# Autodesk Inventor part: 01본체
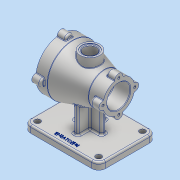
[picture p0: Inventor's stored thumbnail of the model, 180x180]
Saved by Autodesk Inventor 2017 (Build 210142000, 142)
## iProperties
Part Number: 01본체
Material: 알루미늄 6061
Document SubType Name: Modeling
Designer: 222
Density: 2.7 g/cm^3
Appearance: 알루미늄 - 평지
Mass: 1030.13 g
Surface Area: 850.653 cm^2
Volume: 381.528 cm^3
Author: 222
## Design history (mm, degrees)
sketch "스케치1"
  geometry: L1 (0, 0)-(0, 27.5); L2 (0, 27.5)-(-25, 27.5); L3 (-25, 27.5)-(-80, 44); L4 (-80, 44)-(-100, 44); L5 (-100, 44)-(-100, 0); L6 (-100, 0)-(0, 0)
  constraints: 12 end point, 3 perpendicular, 1 parallel, 1 vertical
  dimensions: "d0" = 100 distance of L5.end L1.start; "d1" = 55 diameter of L2 L6; "d2" = 88 diameter of L4 L6; "d3" = 20 distance of L3.end L4.end; "d4" = 25 distance of L1.end L2.end
revolve "회전1" sketch "스케치1" stored, may be unused: angle "d5" = 90 deg
node "작업 평면1"
node "작업 평면2"
sketch "스케치2"
  geometry: L1 (-115, 50)-(15, 50); L2 (15, 50)-(15, -50); L3 (15, -50)-(-115, -50); L4 (-115, -50)-(-115, 50); L5 (-50, 70)-(-50, -70) reference; 3 further points
  constraints: 8 end point, 2 midpoint, 2 parallel, 1 horizontal, 1 horizontal alignment, 1 perpendicular, 1 point on line
  dimensions: "d7" = 130 distance of L1.start L1.end; "d8" = 100 distance of L1.end L2.end
extrude "돌출1" join sketch "스케치2" distance "d9" = 12; taper "d10" = 0 deg
fillet "모깎기1" dims "d11" = 12
sketch "스케치3"
  geometry: L1 (-74, 4)-(-26, 4); L2 (-26, 4)-(-26, -4); L3 (-26, -4)-(-74, -4); L4 (-74, -4)-(-74, 4); L5 (-46, -25)-(-54, -25); L6 (-54, -25)-(-54, 25); L7 (-54, 25)-(-46, 25); L8 (-46, 25)-(-46, -25); L9 (-103, 50)-(3, 50) reference; 6 further points
  constraints: 16 end point, 5 midpoint, 4 parallel, 2 horizontal, 2 horizontal alignment, 2 perpendicular, 2 vertical alignment
  dimensions: "d12" = 8 distance of L6.end L7.end; "d13" = 8 distance of L3.end L1.start; "d14" = 48 distance of L2.end L3.end; "d15" = 50 distance of L7.end L5.start
extrude "돌출2" join sketch "스케치3" stored distance "d16" = 12; taper "d17" = 0 deg
sketch "스케치4"
  geometry: C1 r 7 at (44, 0); 2 further points
  constraints: 1 centre point, 1 horizontal alignment, 1 other
  dimensions: "d18" = 14 diameter of C1
extrude "돌출3" join sketch "스케치4" distance "d19" = 15; taper "d20" = 0 deg
sketch "스케치5"
  geometry: 3 further points
  constraints: 2 horizontal alignment, 1 other
hole "구멍1" sketch "스케치5" at (0, 0) diameter "d21" = 4.134; stored, may be unused: countersink angle "d25" = 90 deg, drill point angle "d27" = 118 deg; dims "d22" = 9, "d23" = 4, "d24" = 2, "d26" = 11
sketch "스케치6"
  geometry: C1 r 7 at (-27.5, 0); A1 r 27.5 centre (0, 0) between (-27.5, 0) and (27.208, 4) reference; 2 further points
  constraints: 1 centre point, 1 point on circle
  dimensions: "d31" = 14 diameter of C1
extrude "돌출4" join sketch "스케치6" distance "d32" = 15; taper "d33" = 0 deg
sketch "스케치7"
  geometry: A1 r 27.5 centre (27.5, 0) between (0, 0) and (0, 0) reference; 3 further points
  constraints: 2 horizontal alignment, 2 point on circle
hole "구멍2" sketch "스케치7" at (0, 0) diameter "d34" = 4.134; stored, may be unused: countersink angle "d38" = 90 deg, drill point angle "d40" = 118 deg; dims "d35" = 9, "d36" = 4, "d37" = 2, "d39" = 11
sketch "스케치8"
  geometry: C1 r 32 at (-44, 0); 1 further point
  constraints: 1 centre point, 1 coincident
  dimensions: "d44" = 64 diameter of C1
extrude "돌출5" cut sketch "스케치8" distance "d45" = 23; taper "d46" = 0 deg
sketch "스케치9"
  geometry: C1 r 26 at (0, 0); 1 further point
  constraints: 1 centre point, 1 coincident
  dimensions: "d47" = 52 diameter of C1
extrude "돌출6" cut sketch "스케치9" distance "d48" = 47; taper "d49" = 0 deg
sketch "스케치10"
  geometry: C1 r 20 at (0, 0); 1 further point
  constraints: 1 centre point, 1 coincident
  dimensions: "d50" = 40 diameter of C1
extrude "돌출7" cut sketch "스케치10" distance "d51" = 30; taper "d52" = 0 deg
chamfer "모따기1" distance "d53" = 1; stored, may be unused: second distance "d54" = 2, angle "d55" = 45 deg
fillet "모깎기2" dims "d56" = 3
node "작업 평면3"
sketch "스케치11"
  geometry: L1 (-100, -43.443)-(-100, -6.978) reference; C1 r 17 at (-50, 0); 1 further point
  constraints: 1 centre point, 1 horizontal alignment
  dimensions: "d58" = 34 diameter of C1; "d59" = 50 distance from line of C1.centre L1
extrude "돌출8" join sketch "스케치11" stored distance "d60" = 30; taper "d61" = 0 deg
sketch "스케치12"
  geometry: C1 r 14 at (0, 0); C2 r 17 at (0, 0) reference; 1 further point
  constraints: 1 centre point, 1 concentric
  dimensions: "d62" = 28 diameter of C1
extrude "돌출9" cut sketch "스케치12" distance "d63" = 1; taper "d64" = 0 deg
sketch "스케치13"
  geometry: C1 r 14 at (0, 0) reference; C2 r 11 at (0, 0); 1 further point
  constraints: 1 centre point, 1 coincident
  dimensions: "d65" = 22 diameter of C2
extrude "돌출10" cut sketch "스케치13" stored distance "d66" = 1; taper "d67" = 0 deg
chamfer "모따기2" distance "d68" = 1; stored, may be unused: second distance "d69" = 2, angle "d70" = 45 deg
sketch "스케치14"
  geometry: C1 r 5 at (-103, -38); A1 r 12 centre (-103, -38) between (-115, -38) and (-103, -50) reference; 1 further point
  constraints: 1 centre point, 1 concentric
  dimensions: "d71" = 10 diameter of C1
extrude "돌출11" cut sketch "스케치14" stored distance "d72" = 1; taper "d73" = 0 deg
node "작업 평면4"
fillet "모깎기3" dims "d74" = 3
fillet "모깎기4" dims "d75" = 3
fillet "모깎기5" dims "d76" = 3
fillet "모깎기6" dims "d77" = 3
fillet "모깎기7" dims "d78" = 3
fillet "모깎기8" dims "d79" = 1
node "작업 평면5"
sketch "스케치15"
  geometry: L1 (15, -38)-(15, 38) reference; L2 (-103, -50)-(3, -50) reference; 2 further points
  constraints: 1 other
  dimensions: "d81" = 65 distance from line of L1 point (-50, -40); "d82" = 10 distance from line of L2 point (-50, -40)
feature "엠보싱1" sketch "스케치15" dims "d0" = 100, "d1" = 55, "d2" = 88, "d3" = 20, "d4" = 25, "d10" = 0, "d83" = 0.5, "d84" = 0
fillet "모깎기9" dims "d85" = 1
node "솔리드1"
pattern_circular "원형 패턴1" dims angle "d29" = 360 deg
pattern_circular "원형 패턴2" dims angle "d42" = 360 deg
mirror "미러1"
mirror "미러2"
other parameters: "d6" = -82, "d57" = 45, "d80" = 5.5
